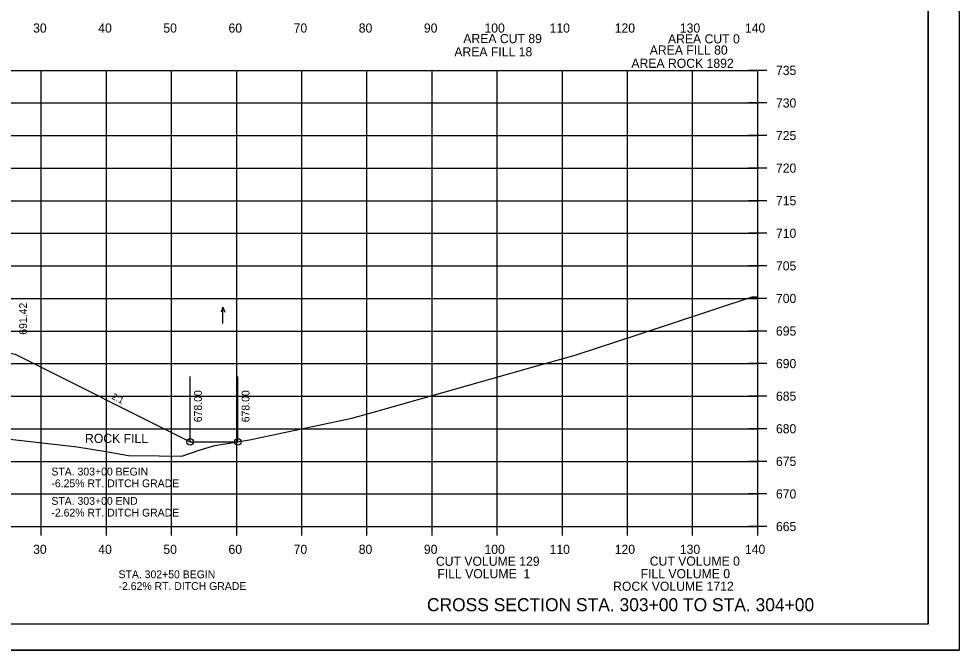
# Model space of a CAD drawing. Extents: x 1370515 to 1370849, y 383299 to 386073.
# Drawn here: x 1370704.3 to 1370848.7, y 383939.4 to 384036.3 of the extents above; entities that cross this region are included whole.
import ezdxf

# ---------------------------------------------------------------- set-up
doc = ezdxf.new("R2010")
doc.units = 0
for name, color, linetype in [('R_Axis', 7, 'Continuous'), ('R_Axis Annot', 7, 'Continuous'), ('R_Border', 7, 'Continuous'), ('R_Draft', 7, 'Continuous'), ('R_Drive', 7, 'Continuous'), ('R_Exist Surface', 7, 'Continuous'), ('R_Fin Surface', 7, 'Continuous'), ('R_Grid', 7, 'Continuous'), ('R_No Plot', 7, 'Continuous'), ('R_Water Annot', 7, 'Continuous'), ('R_Xsect Elev', 7, 'Continuous'), ('R_Xsect Slope', 7, 'Continuous')]:
    doc.layers.add(name, color=color, linetype=linetype)

msp = doc.modelspace()

# ---------------------------------------------------------------- linework, layer by layer
at = {"layer": 'R_Axis'}
for p, q in [((1370819.2, 384028.42), (1370816.4, 384028.42)), ((1370817.8, 383958.42), (1370817.8, 384028.42)), ((1370819.2, 384023.42), (1370816.4, 384023.42)), ((1370819.2, 384018.42), (1370816.4, 384018.42)), ((1370819.2, 384013.42), (1370816.4, 384013.42)), ((1370819.2, 384008.42), (1370816.4, 384008.42)), ((1370819.2, 384003.42), (1370816.4, 384003.42)), ((1370819.2, 383998.42), (1370816.4, 383998.42)), ((1370819.2, 383993.42), (1370816.4, 383993.42)), ((1370819.2, 383988.42), (1370816.4, 383988.42)), ((1370819.2, 383983.42), (1370816.4, 383983.42)), ((1370819.2, 383978.42), (1370816.4, 383978.42)), ((1370819.2, 383973.42), (1370816.4, 383973.42)), ((1370819.2, 383968.42), (1370816.4, 383968.42)), ((1370819.2, 383963.42), (1370816.4, 383963.42)), ((1370707.8, 383957.02), (1370707.8, 383959.82)), ((1370717.8, 383957.02), (1370717.8, 383959.82)), ((1370727.8, 383957.02), (1370727.8, 383959.82)), ((1370737.8, 383957.02), (1370737.8, 383959.82)), ((1370747.8, 383957.02), (1370747.8, 383959.82)), ((1370757.8, 383957.02), (1370757.8, 383959.82)), ((1370767.8, 383957.02), (1370767.8, 383959.82)), ((1370777.8, 383957.02), (1370777.8, 383959.82)), ((1370787.8, 383957.02), (1370787.8, 383959.82)), ((1370797.8, 383957.02), (1370797.8, 383959.82)), ((1370807.8, 383957.02), (1370807.8, 383959.82)), ((1370817.8, 383957.02), (1370817.8, 383959.82)), ((1370537.8, 383958.42), (1370817.8, 383958.42)), ((1370819.2, 383958.42), (1370816.4, 383958.42))]:
    msp.add_line(p, q, dxfattribs=at)
at = {"layer": 'R_Border'}
for q in [(1370843.98, 384148.88), (1370527.8, 383943.42)]:
    msp.add_line((1370843.98, 383943.42), q, dxfattribs=at)
at = {"layer": 'R_Exist Surface'}
msp.add_lwpolyline([(1370702.07, 383971.95), (1370713.31, 383970.65), (1370717.69, 383969.94), (1370721.17, 383969.31), (1370725.88, 383969.25), (1370729.35, 383969.2), (1370732.17, 383970.21), (1370734.45, 383970.85), (1370739.77, 383971.72), (1370755.5, 383975.07), (1370759.17, 383976.07), (1370783.55, 383982.96), (1370789.22, 383984.56), (1370789.91, 383984.76), (1370799.44, 383987.89), (1370816.96, 383993.66), (1370817.42, 383993.65), (1370817.8, 383993.65)], dxfattribs=at)
at = {"layer": 'R_Fin Surface'}
msp.add_lwpolyline([(1370630.25, 383984.23), (1370647.83, 383983.52), (1370651.8, 383984.85), (1370652.52, 383985.02), (1370657.8, 383986.35), (1370665.8, 383986.67), (1370677.8, 383986.91), (1370689.8, 383986.67), (1370697.8, 383986.35), (1370703.09, 383985.02), (1370703.8, 383984.85), (1370730.65, 383971.42), (1370737.96, 383971.42)], dxfattribs=at)
at = {"layer": 'R_Grid'}
for p, q in [((1370537.8, 384028.42), (1370817.8, 384028.42)), ((1370707.8, 383958.42), (1370707.8, 384028.42)), ((1370717.8, 383958.42), (1370717.8, 384028.42)), ((1370727.8, 383958.42), (1370727.8, 384028.42)), ((1370737.8, 383958.42), (1370737.8, 384028.42)), ((1370747.8, 383958.42), (1370747.8, 384028.42)), ((1370757.8, 383958.42), (1370757.8, 384028.42)), ((1370767.8, 383958.42), (1370767.8, 384028.42)), ((1370777.8, 383958.42), (1370777.8, 384028.42)), ((1370787.8, 383958.42), (1370787.8, 384028.42)), ((1370797.8, 383958.42), (1370797.8, 384028.42)), ((1370807.8, 383958.42), (1370807.8, 384028.42)), ((1370817.8, 383958.42), (1370817.8, 384028.42)), ((1370537.8, 384023.42), (1370817.8, 384023.42)), ((1370537.8, 384018.42), (1370817.8, 384018.42)), ((1370537.8, 384013.42), (1370817.8, 384013.42)), ((1370537.8, 384008.42), (1370817.8, 384008.42)), ((1370537.8, 384003.42), (1370817.8, 384003.42)), ((1370537.8, 383998.42), (1370817.8, 383998.42)), ((1370537.8, 383993.42), (1370817.8, 383993.42)), ((1370537.8, 383988.42), (1370817.8, 383988.42)), ((1370537.8, 383983.42), (1370817.8, 383983.42)), ((1370537.8, 383978.42), (1370817.8, 383978.42)), ((1370537.8, 383973.42), (1370817.8, 383973.42)), ((1370537.8, 383968.42), (1370817.8, 383968.42)), ((1370537.8, 383963.42), (1370817.8, 383963.42)), ((1370537.8, 383958.42), (1370817.8, 383958.42))]:
    msp.add_line(p, q, dxfattribs=at)
at = {"layer": 'R_No Plot'}
msp.add_line((1370515.4, 383939.44), (1370848.73, 383939.44), dxfattribs=at)
for points in [[(1370515.39, 384152.78), (1370848.73, 384152.78), (1370848.73, 383939.44), (1370515.39, 383939.44)], [(1370761.72, 384148.88), (1370761.72, 384139), (1370797.45, 384139), (1370797.45, 384136.08), (1370820.65, 384136.08), (1370820.65, 384112.87), (1370843.98, 384112.87), (1370843.98, 383943.42), (1370527.8, 383943.42), (1370527.8, 384148.88)]]:
    msp.add_lwpolyline(points, close=True, dxfattribs=at)
for centre in [(1370730.65, 383971.42), (1370730.65, 383971.42), (1370737.96, 383971.42)]:
    msp.add_circle(centre, 0.5, dxfattribs=at)
at = {"layer": 'R_Water Annot'}
for p, q in [((1370735.69, 383992.07), (1370735.41, 383991.3)), ((1370735.69, 383989.56), (1370735.69, 383992.07)), ((1370735.69, 383992.07), (1370735.97, 383991.3))]:
    msp.add_line(p, q, dxfattribs=at)
at = {"layer": 'R_Xsect Elev'}
for p, q in [((1370730.65, 383971.42), (1370730.65, 383981.42)), ((1370737.96, 383971.42), (1370737.96, 383981.42))]:
    msp.add_line(p, q, dxfattribs=at)

# ---------------------------------------------------------------- texts
at = {"layer": 'R_Axis Annot'}
for s, p in [('30', (1370706.54, 384034.22)), ('40', (1370716.54, 384034.22)), ('50', (1370726.54, 384034.22)), ('60', (1370736.54, 384034.22)), ('70', (1370746.54, 384034.22)), ('80', (1370756.54, 384034.22)), ('90', (1370766.54, 384034.22)), ('100', (1370775.84, 384034.22)), ('110', (1370785.84, 384034.22)), ('120', (1370795.84, 384034.22)), ('130', (1370805.84, 384034.22)), ('140', (1370815.84, 384034.22)), ('AREA CUT 89', (1370772.59, 384032.6)), ('AREA CUT 0', (1370804.02, 384032.56)), ('AREA FILL 80', (1370801.22, 384030.84)), ('AREA FILL 18', (1370771.21, 384030.58)), ('AREA ROCK 1892', (1370798.4, 384028.81)), ('735', (1370820.6, 384027.72)), ('730', (1370820.6, 384022.72)), ('725', (1370820.6, 384017.72)), ('720', (1370820.6, 384012.72)), ('715', (1370820.6, 384007.72)), ('710', (1370820.6, 384002.72)), ('705', (1370820.6, 383997.72)), ('700', (1370820.6, 383992.72)), ('695', (1370820.6, 383987.72)), ('690', (1370820.6, 383982.72)), ('685', (1370820.6, 383977.72)), ('680', (1370820.6, 383972.72)), ('ROCK FILL', (1370714.51, 383971.24)), ('675', (1370820.6, 383967.72)), ('670', (1370820.6, 383962.72)), ('665', (1370820.6, 383957.72)), ('30', (1370706.54, 383954.22)), ('40', (1370716.54, 383954.22)), ('50', (1370726.54, 383954.22)), ('60', (1370736.54, 383954.22)), ('70', (1370746.54, 383954.22)), ('80', (1370756.54, 383954.22)), ('90', (1370766.54, 383954.22)), ('100', (1370775.84, 383954.22)), ('110', (1370785.84, 383954.22)), ('120', (1370795.84, 383954.22)), ('130', (1370805.84, 383954.22)), ('140', (1370815.84, 383954.22)), ('CUT VOLUME 129', (1370768.39, 383952.39)), ('CUT VOLUME 0', (1370801.22, 383952.41)), ('FILL VOLUME  1', (1370768.61, 383950.48)), ('FILL VOLUME 0', (1370799.82, 383950.48)), ('ROCK VOLUME 1712', (1370795.6, 383948.55))]:
    msp.add_text(s, height=1.4, dxfattribs=at).set_placement(p)
at = {"layer": 'R_Draft'}
msp.add_text('CROSS SECTION STA. 303+00 TO STA. 304+00', height=2, dxfattribs=at).set_placement((1370767.01, 383945.42))
at = {"layer": 'R_Drive'}
for s, p in [('STA. 303+00 BEGIN', (1370709.35, 383966.25)), ('-6.25% RT. DITCH GRADE', (1370709.35, 383964.45)), ('STA. 303+00 END', (1370709.35, 383961.75)), ('-2.62% RT. DITCH GRADE', (1370709.35, 383959.95)), ('STA. 302+50 BEGIN', (1370719.66, 383950.48)), ('-2.62% RT. DITCH GRADE', (1370719.66, 383948.68))]:
    msp.add_text(s, height=1.2, dxfattribs=at).set_placement(p)
at = {"layer": 'R_No Plot'}
for p in [(1370816.92, 383993.61), (1370789.87, 383984.71), (1370755.46, 383975.02), (1370713.27, 383970.6), (1370734.4, 383970.8), (1370721.13, 383969.26), (1370729.3, 383969.15)]:
    msp.add_text('+', height=0.1, dxfattribs=at).set_placement(p)
at = {"layer": 'R_Xsect Elev'}
for s, p in [('691.42', (1370705.6, 383987.85)), ('678.00', (1370732.45, 383974.42)), ('678.00', (1370739.76, 383974.42))]:
    msp.add_text(s, height=1.2, rotation=90, dxfattribs=at).set_placement(p)
at = {"layer": 'R_Xsect Slope'}
msp.add_text('2:1', height=1, rotation=333.4349, dxfattribs=at).set_placement((1370718.5, 383978.06))

doc.saveas('drawing.dxf')
